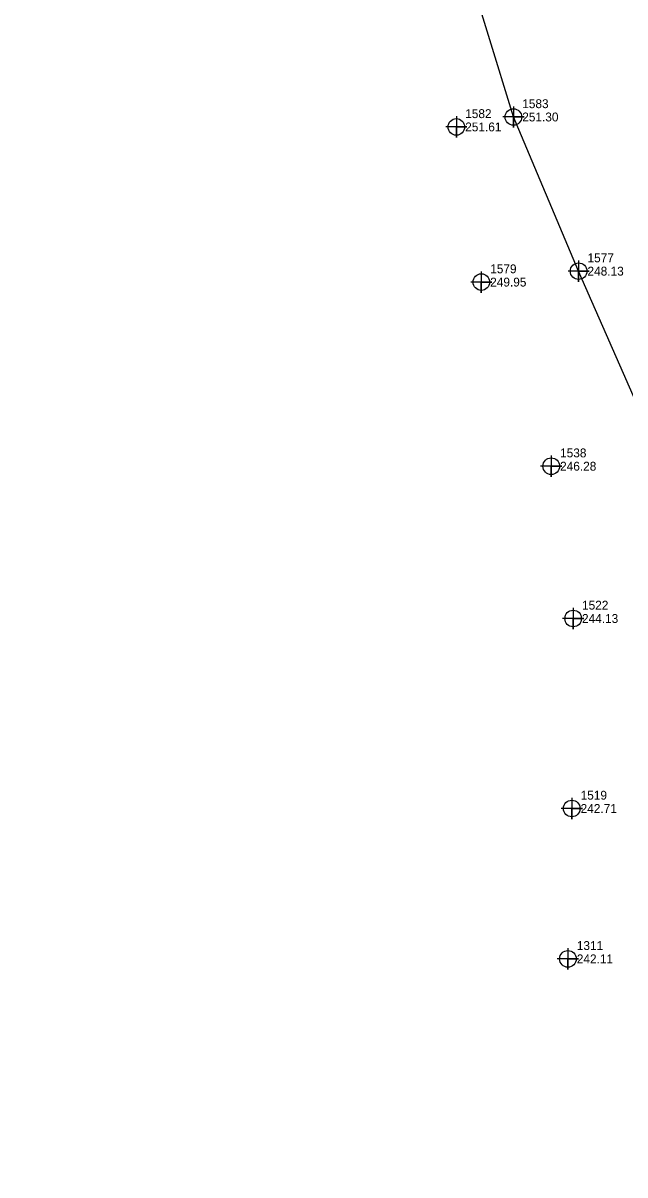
# Model space of a CAD drawing. Extents: x 2130962 to 2131465, y 643052 to 644206.
# Drawn here: x 2131000.7 to 2131170.6, y 643306.2 to 643631.2 of the extents above; entities that cross this region are included whole.
import ezdxf

# ---------------------------------------------------------------- set-up
doc = ezdxf.new("R2010")
doc.units = 0
for name, color, linetype in [('Exist DTM Breakline', 7, 'Continuous'), ('Exist DTM Breakline Cogo Elevation', 7, 'Continuous'), ('Exist DTM Breakline Cogo Number', 7, 'Continuous'), ('Exist DTM Breakline Cogo Point CELL', 7, 'Continuous'), ('Exist DTM Regular Point CELL', 7, 'Continuous'), ('Exist DTM Regular Point Cogo Elevation', 7, 'Continuous'), ('Exist DTM Regular Point Cogo Number', 7, 'Continuous'), ('Exist Roads EOP', 7, 'Continuous'), ('Exist Roads EOT', 7, 'Continuous')]:
    doc.layers.add(name, color=color, linetype=linetype)

msp = doc.modelspace()

# ---------------------------------------------------------------- linework, layer by layer
at = {"layer": 'Exist DTM Breakline'}
msp.add_lwpolyline([(2131000.7408, 643235.0731), (2131050.2503, 643235.0771), (2131099.3971, 643233.3967), (2131102.4734, 643233.467), (2131117.9784, 643240.6457), (2131141.4902, 643260.2289), (2131148.9668, 643267.309), (2131161.3925, 643274.3195), (2131169.1458, 643283.2692), (2131172.0772, 643292.493), (2131174.434, 643316.7319), (2131174.0607, 643347.0813), (2131174.2633, 643367.3367), (2131180.4607, 643413.966), (2131183.0424, 643464.7744), (2131179.7562, 643510.5479), (2131157.5016, 643561.2065), (2131139.0887, 643604.6918), (2131124.996, 643650.6897)], dxfattribs=at)
at = {"layer": 'Exist DTM Breakline Cogo Point CELL'}
for points in [[(2131139.0887, 643607.6918), (2131139.0887, 643601.6918), (2131139.0887, 643604.6918), (2131142.0887, 643604.6918), (2131136.0887, 643604.6918)], [(2131157.5016, 643564.2065), (2131157.5016, 643558.2065), (2131157.5016, 643561.2065), (2131160.5016, 643561.2065), (2131154.5016, 643561.2065)]]:
    msp.add_lwpolyline(points, dxfattribs=at)
for centre in [(2131139.0887, 643604.6918), (2131157.5016, 643561.2065)]:
    msp.add_circle(centre, 2.344, dxfattribs=at)
at = {"layer": 'Exist DTM Regular Point CELL'}
for points in [[(2131122.9929, 643604.884), (2131122.9929, 643598.884), (2131122.9929, 643601.884), (2131125.9929, 643601.884), (2131119.9929, 643601.884)], [(2131130.045, 643561.1138), (2131130.045, 643555.1138), (2131130.045, 643558.1138), (2131133.045, 643558.1138), (2131127.045, 643558.1138)], [(2131149.7664, 643509.1773), (2131149.7664, 643503.1773), (2131149.7664, 643506.1773), (2131152.7664, 643506.1773), (2131146.7664, 643506.1773)], [(2131155.9505, 643466.2174), (2131155.9505, 643460.2174), (2131155.9505, 643463.2174), (2131158.9505, 643463.2174), (2131152.9505, 643463.2174)], [(2131155.5621, 643412.6128), (2131155.5621, 643406.6128), (2131155.5621, 643409.6128), (2131158.5621, 643409.6128), (2131152.5621, 643409.6128)], [(2131154.4832, 643370.1942), (2131154.4832, 643364.1942), (2131154.4832, 643367.1942), (2131157.4832, 643367.1942), (2131151.4832, 643367.1942)]]:
    msp.add_lwpolyline(points, dxfattribs=at)
for centre in [(2131122.9929, 643601.884), (2131130.045, 643558.1138), (2131149.7664, 643506.1773), (2131155.9505, 643463.2174), (2131155.5621, 643409.6128), (2131154.4832, 643367.1942)]:
    msp.add_circle(centre, 2.344, dxfattribs=at)
at = {"layer": 'Exist Roads EOP'}
msp.add_spline([(2131166.2495, 643216.6951), (2131171.8131, 643218.7244), (2131182.3713, 643223.9726), (2131191.8117, 643231.1489), (2131200.5013, 643239.6993), (2131208.8071, 643249.0697), (2131216.0672, 643259.0032), (2131218.7188, 643264.347), (2131220.5363, 643270.0958), (2131222.8445, 643282.0077), (2131224.3583, 643293.9245), (2131224.8763, 643317.7904), (2131222.0632, 643367.6716), (2131218.5448, 643416.8114), (2131214.3187, 643466.3462), (2131209.1735, 643515.6666), (2131202.7939, 643565.1545), (2131195.0475, 643613.9937), (2131186.4014, 643662.4763), (2131176.0113, 643711.405), (2131164.6154, 643759.8896), (2131151.874, 643807.8526), (2131137.8554, 643855.4065), (2131122.5733, 643902.8574), (2131105.9622, 643949.4862), (2131091.5349, 643988.0437)], degree=3, dxfattribs=at)
at = {"layer": 'Exist Roads EOT'}
msp.add_spline([(2131166.718, 643215.2083), (2131172.3866, 643217.1804), (2131211.4056, 643247.1499), (2131223.758, 643268.7314), (2131228.3848, 643317.935), (2131225.533, 643367.8628), (2131222.2486, 643417.1873), (2131217.9619, 643466.6275), (2131212.8794, 643516.2377), (2131206.5633, 643565.5764), (2131198.9021, 643614.6757), (2131189.6851, 643663.4055), (2131179.3985, 643712.1311), (2131168.3085, 643760.7185), (2131155.755, 643808.9129), (2131141.6748, 643856.5528), (2131126.5354, 643904.2758), (2131110.3559, 643951.0191), (2131092.4533, 643998.1348), (2131073.722, 644043.631), (2131053.1654, 644089.359), (2131032.0052, 644134.0908), (2131009.0644, 644179.3802)], degree=3, dxfattribs=at)

# ---------------------------------------------------------------- texts
at = {"layer": 'Exist DTM Breakline Cogo Elevation'}
for s, p in [('251.30', (2131141.5887, 643603.4418)), ('248.13', (2131160.0016, 643559.9565))]:
    msp.add_text(s, height=2.5, dxfattribs=at).set_placement(p)
at = {"layer": 'Exist DTM Breakline Cogo Number'}
for s, p in [('1583', (2131141.5887, 643607.1918)), ('1577', (2131160.0016, 643563.7065))]:
    msp.add_text(s, height=2.5, dxfattribs=at).set_placement(p)
at = {"layer": 'Exist DTM Regular Point Cogo Elevation'}
for s, p in [('251.61', (2131125.4929, 643600.634)), ('249.95', (2131132.545, 643556.8638)), ('246.28', (2131152.2664, 643504.9273)), ('244.13', (2131158.4505, 643461.9674)), ('242.71', (2131158.0621, 643408.3628)), ('242.11', (2131156.9832, 643365.9442))]:
    msp.add_text(s, height=2.5, dxfattribs=at).set_placement(p)
at = {"layer": 'Exist DTM Regular Point Cogo Number'}
for s, p in [('1582', (2131125.4929, 643604.384)), ('1579', (2131132.545, 643560.6138)), ('1538', (2131152.2664, 643508.6773)), ('1522', (2131158.4505, 643465.7174)), ('1519', (2131158.0621, 643412.1128)), ('1311', (2131156.9832, 643369.6942))]:
    msp.add_text(s, height=2.5, dxfattribs=at).set_placement(p)

doc.saveas('drawing.dxf')
